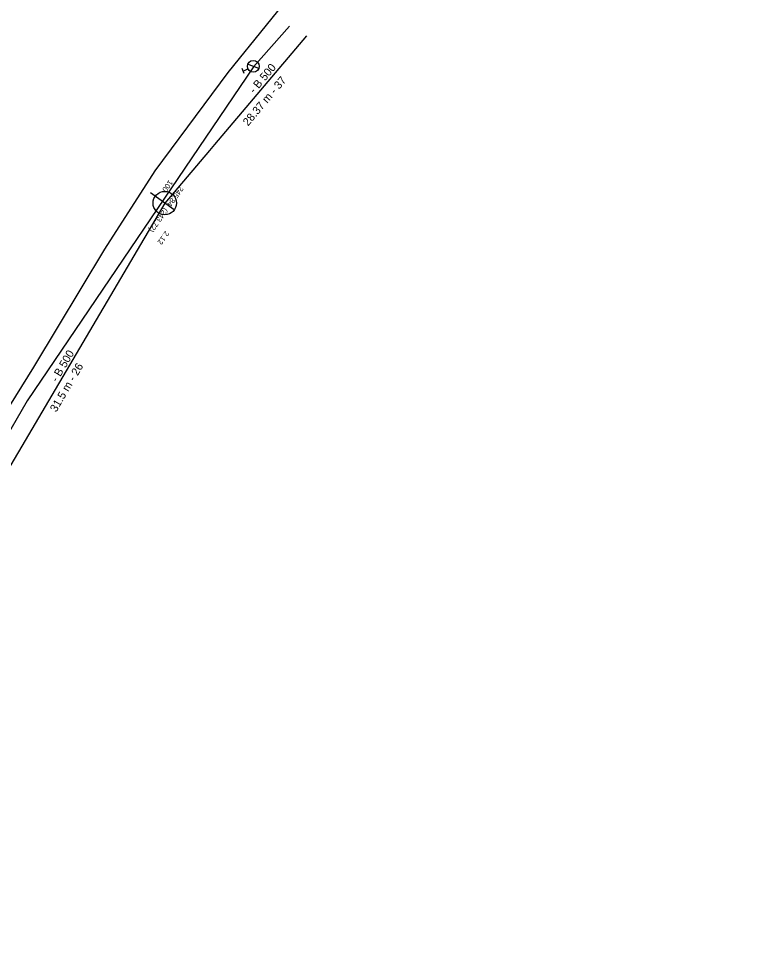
# Model space of a CAD drawing. Extents: x -600636 to -600148, y -1203980 to -1203569.
# Drawn here: x -600209.8 to -600148.1, y -1203718.3 to -1203639.7 of the extents above; entities that cross this region are included whole.
import ezdxf

# ---------------------------------------------------------------- set-up
doc = ezdxf.new("R2010")
doc.units = 0
for name, color, linetype in [('Cetin zam průběh', 7, 'Continuous'), ('Implicitní', 7, 'Continuous'), ('VaK Břeclav_kanalizace', 7, 'Continuous'), ('VaK Břeclav_kanalizace_popis', 7, 'Continuous'), ('Vak Břeclav_vodovod', 7, 'Continuous')]:
    doc.layers.add(name, color=color, linetype=linetype)

# ---------------------------------------------------------------- blocks, each defined once
blk = doc.blocks.new('MoSymbol 2')
at = {"layer": 'Implicitní'}
blk.add_line((0, 0.0005), (0, -0.00075), dxfattribs=at)
blk.add_circle((0, 0), 0.0005, dxfattribs=at)
blk = doc.blocks.new('MoSymbol 3')
at = {"layer": 'Implicitní'}
for p, q in [((-0.000225, 0.00095), (0.000225, 0.00095)), ((0, 0.00095), (0, 0.0005)), ((-0.000365, -0.000365), (0.000365, 0.000365))]:
    blk.add_line(p, q, dxfattribs=at)
blk.add_circle((0, 0), 0.0005, dxfattribs=at)

msp = doc.modelspace()

# ---------------------------------------------------------------- linework, layer by layer
at = {"layer": 'Cetin zam průběh'}
msp.add_lwpolyline([(-600238.73, -1203718.32), (-600229.65, -1203703.65), (-600215.97, -1203681.5), (-600208.47, -1203669.5), (-600202.43, -1203659.43), (-600198.13, -1203652.76), (-600191.9, -1203644.36), (-600182.08, -1203632.22), (-600175.22, -1203624.74), (-600171.57, -1203620.8), (-600170.9, -1203620.45), (-600170.66, -1203619.82), (-600162.89, -1203611.32), (-600154.76, -1203602.44), (-600154.39, -1203600.87), (-600148.06, -1203593.79)], dxfattribs=at)
at = {"layer": 'VaK Břeclav_kanalizace'}
msp.add_line((-600197.304, -1203655.497), (-600213.29, -1203682.64), dxfattribs=at)
msp.add_lwpolyline([(-600185.193, -1203641.22), (-600193.072, -1203650.508), (-600193.496, -1203651.008), (-600197.304, -1203655.497)], dxfattribs=at)
at = {"layer": 'Vak Břeclav_vodovod'}
msp.add_line((-600186.652, -1203640.406), (-600189.723, -1203643.886), dxfattribs=at)
msp.add_lwpolyline([(-600189.723, -1203643.886), (-600209.039, -1203672.378), (-600226.824, -1203703.137), (-600234.083, -1203715.623)], dxfattribs=at)

# ---------------------------------------------------------------- block references
at = {"layer": 'VaK Břeclav_kanalizace', "xscale": 1999.750031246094, "yscale": 1999.7500312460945, "rotation": -125.40153829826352}
msp.add_blockref('MoSymbol 2', (-600197.304, -1203655.497), dxfattribs=at)
at = {"layer": 'Vak Břeclav_vodovod', "xscale": 999.875015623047, "yscale": 999.875015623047, "rotation": 115.05282631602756}
msp.add_blockref('MoSymbol 3', (-600189.749, -1203643.831), dxfattribs=at)

# ---------------------------------------------------------------- texts
at = {"layer": 'VaK Břeclav_kanalizace_popis'}
for s, height, rotation, p in [('- B 500', 0.6824, 49.69309, (-600189.662, -1203646.205)), ('28.37 m - 37', 0.68241, 49.69309, (-600190.192, -1203648.968)), ('245,84  (243,72)', 0.45494, 234.59846, (-600196.031, -1203654.02)), ('100', 0.4549, 234.59846, (-600196.946, -1203653.494)), ('2.12', 0.4549, 234.59846, (-600197.254, -1203657.842)), ('- B 500', 0.6824, 59.50384, (-600206.501, -1203670.83)), ('31.5 m - 26', 0.68241, 59.50384, (-600206.572, -1203673.379))]:
    msp.add_text(s, height=height, rotation=rotation, dxfattribs=at).set_placement(p)

doc.saveas('drawing.dxf')
